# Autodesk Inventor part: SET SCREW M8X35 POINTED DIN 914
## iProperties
IsCustomPart: 1
Created: 2006-02
Part Number: SET SCREW M8X35 POINTED DIN 914
Material: Steel, Mild
Description: Hexagon Socket Set Screw
Document SubType Name: Modeling
Standard: DIN 914
Designer: Andy Moles
Standards Organization: DIN
Language: en-US
Size Designation: M8 x 35
Categories: <MemberInstance><Categories><Category DisplayName="Fasteners" InternalName="e4da775c-781d-43d5-af7c-5136215cf5a6" Mnemonic="FSTN"><Category DisplayName="Bolts"
Density: 1 g/cm^3
Author: Andy Moles
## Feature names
1. Body [Revolution]
2. Slot [Extrusion]
3. Chamfer1
4. Chamfer2
